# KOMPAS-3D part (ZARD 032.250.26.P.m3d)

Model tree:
1. Плоскость XY
2. Плоскость ZX
3. Плоскость ZY
4. Ось X
5. Ось Y
6. Ось Z
7. Начало координат
8. Булева операция:1
9. Булева операция:2
10. Булева операция:3
11. Булева операция:4
